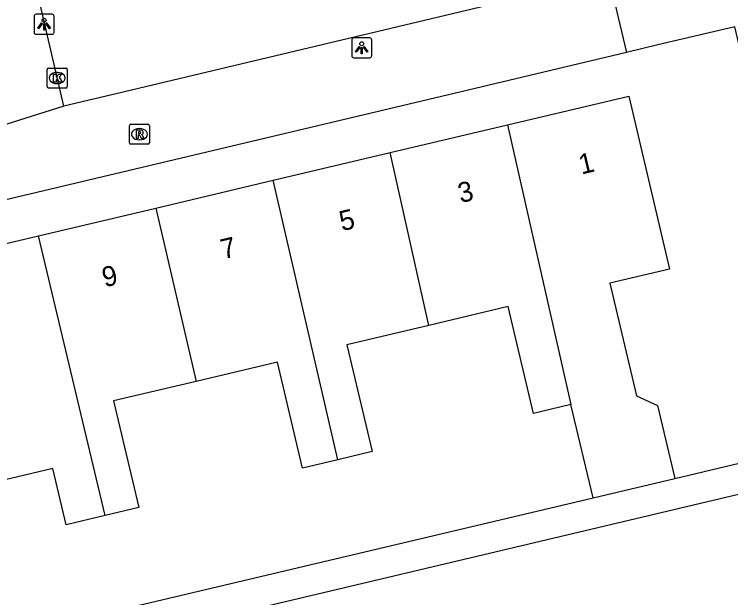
# Model space of a CAD drawing. Extents: x 158038 to 159242, y 380133 to 381214.
# Drawn here: x 158523.41 to 158559.26, y 380724.66 to 380753.87 of the extents above; entities that cross this region are included whole.
import ezdxf

# ---------------------------------------------------------------- set-up
doc = ezdxf.new("R2010")
doc.units = 0
for name, color, linetype in [('IMGEO_Kolk', 7, 'Continuous'), ('IMGEO_Lichtpunt', 7, 'Continuous'), ('IMGEO_Pand', 7, 'Continuous'), ('IMGEO_Pand_nummerreeks', 7, 'Continuous'), ('IMGEO_Rijbaan_lokaal_open', 7, 'Continuous'), ('IMGEO_Rioolput', 7, 'Continuous'), ('IMGEO_Voetpad_open', 7, 'Continuous')]:
    doc.layers.add(name, color=color, linetype=linetype)

msp = doc.modelspace()

# ---------------------------------------------------------------- linework, layer by layer
at = {"layer": 'IMGEO_Kolk'}
for p, q in [((158525.053, 380750.257), (158525.053, 380751.109)), ((158525.128, 380751.183), (158525.98, 380751.183)), ((158525.541, 380750.963), (158525.566, 380750.963)), ((158526.054, 380751.109), (158526.054, 380750.257)), ((158525.98, 380750.183), (158525.128, 380750.183)), ((158525.564, 380750.403), (158525.539, 380750.403))]:
    msp.add_line(p, q, dxfattribs=at)
for points in [[(158525.053, 380750.257), (158525.053, 380751.109)], [(158525.128, 380751.183), (158525.98, 380751.183)], [(158526.054, 380751.109), (158526.054, 380750.257)], [(158525.374, 380750.883), (158525.497, 380750.883), (158525.497, 380750.732), (158525.627, 380750.883), (158525.791, 380750.883), (158525.645, 380750.732), (158525.798, 380750.483), (158525.646, 380750.483), (158525.561, 380750.647), (158525.497, 380750.58), (158525.497, 380750.483), (158525.374, 380750.483), (158525.374, 380750.883)], [(158525.98, 380750.183), (158525.128, 380750.183)]]:
    msp.add_lwpolyline(points, dxfattribs=at)
for centre, start, end in [((158525.13, 380751.107), 91.552, 178.448), ((158525.13, 380751.107), 91.552, 178.448), ((158525.978, 380751.107), 1.552, 88.448), ((158525.978, 380751.107), 1.552, 88.448), ((158525.13, 380750.259), 181.552, 268.448), ((158525.13, 380750.259), 181.552, 268.448), ((158525.978, 380750.259), 271.552, 358.448), ((158525.978, 380750.259), 271.552, 358.448)]:
    msp.add_arc(centre, 0.0765, start, end, dxfattribs=at)
for centre, major_axis, ratio, start_param, end_param in [((158525.54, 380750.683), (-0.387, 0.002), 0.722429, 4.712389, 7.853982), ((158525.565, 380750.683), (-0.39, 0.002), 0.717154, 1.570796, 4.712389)]:
    msp.add_ellipse(centre, major_axis=major_axis, ratio=ratio, start_param=start_param, end_param=end_param, dxfattribs=at)
at = {"layer": 'IMGEO_Lichtpunt'}
for p, q in [((158524.4, 380753.779), (158524.4, 380752.972)), ((158524.4, 380753.779), (158524.4, 380752.972)), ((158525.302, 380753.874), (158524.494, 380753.874)), ((158525.302, 380753.874), (158524.494, 380753.874)), ((158525.396, 380752.972), (158525.396, 380753.779)), ((158525.396, 380752.972), (158525.396, 380753.779)), ((158524.494, 380752.878), (158525.302, 380752.878)), ((158524.494, 380752.878), (158525.302, 380752.878)), ((158541.199, 380752.696), (158540.391, 380752.696)), ((158541.199, 380752.696), (158540.391, 380752.696)), ((158540.297, 380752.601), (158540.297, 380751.794)), ((158540.297, 380752.601), (158540.297, 380751.794)), ((158541.293, 380751.794), (158541.293, 380752.601)), ((158541.293, 380751.794), (158541.293, 380752.601)), ((158540.391, 380751.7), (158541.199, 380751.7)), ((158540.391, 380751.7), (158541.199, 380751.7))]:
    msp.add_line(p, q, dxfattribs=at)
for points in [[(158524.774, 380753.443), (158524.813, 380753.415), (158524.625, 380753.153), (158524.587, 380753.18), (158524.774, 380753.443)], [(158524.986, 380753.415), (158525.024, 380753.442), (158525.211, 380753.18), (158525.172, 380753.152), (158524.986, 380753.415)], [(158524.876, 380753.395), (158524.923, 380753.395), (158524.923, 380753.073), (158524.876, 380753.073), (158524.876, 380753.395)], [(158540.671, 380752.265), (158540.71, 380752.237), (158540.522, 380751.975), (158540.484, 380752.002), (158540.671, 380752.265)], [(158540.773, 380752.217), (158540.82, 380752.217), (158540.82, 380751.895), (158540.773, 380751.895), (158540.773, 380752.217)], [(158540.883, 380752.237), (158540.921, 380752.264), (158541.108, 380752.002), (158541.069, 380751.974), (158540.883, 380752.237)]]:
    msp.add_lwpolyline(points, dxfattribs=at)
for centre in [(158524.899, 380753.577), (158540.796, 380752.399)]:
    msp.add_circle(centre, 0.0994, dxfattribs=at)
for centre, start, end in [((158524.494, 380753.779), 90, 180), ((158524.494, 380753.779), 90, 180), ((158525.302, 380753.779), 0, 90), ((158525.302, 380753.779), 0, 90), ((158524.494, 380752.972), 180, 270), ((158524.494, 380752.972), 180, 270), ((158525.302, 380752.972), 270, 0), ((158525.302, 380752.972), 270, 360), ((158540.391, 380752.601), 90, 180), ((158540.391, 380752.601), 90, 180), ((158541.199, 380752.601), 0, 90), ((158541.199, 380752.601), 0, 90), ((158540.391, 380751.794), 180, 270), ((158540.391, 380751.794), 180, 270), ((158541.199, 380751.794), 270, 0), ((158541.199, 380751.794), 270, 360)]:
    msp.add_arc(centre, 0.0946, start, end, dxfattribs=at)
at = {"layer": 'IMGEO_Pand'}
for points in [[(158548.086, 380748.344), (158554.154, 380749.781), (158556.205, 380741.118), (158553.218, 380740.411), (158554.554, 380734.767), (158555.592, 380734.295), (158556.459, 380730.636)], [(158542.212, 380746.953), (158548.086, 380748.344)], [(158548.086, 380748.344), (158551.265, 380734.335)], [(158536.368, 380745.569), (158542.212, 380746.953)], [(158544.152, 380738.299), (158542.212, 380746.953)], [(158530.486, 380744.176), (158536.368, 380745.569)], [(158539.599, 380731.57), (158536.368, 380745.569)], [(158524.623, 380742.787), (158530.486, 380744.176)], [(158530.486, 380744.176), (158532.5, 380735.491)], [(158518.537, 380741.346), (158524.623, 380742.787)], [(158527.954, 380728.778), (158524.623, 380742.787)], [(158527.954, 380728.778), (158525.999, 380728.315), (158525.332, 380731.135), (158521.188, 380730.153), (158520.589, 380732.683), (158519.689, 380736.481), (158519.042, 380739.212)], [(158551.265, 380734.335), (158549.395, 380733.892), (158548.128, 380739.241), (158544.152, 380738.299)], [(158544.152, 380738.299), (158540.055, 380737.329), (158541.322, 380731.978), (158539.599, 380731.57)], [(158539.599, 380731.57), (158537.828, 380731.151), (158536.571, 380736.455), (158532.5, 380735.491)], [(158532.5, 380735.491), (158528.377, 380734.514), (158529.641, 380729.177), (158527.954, 380728.778)], [(158552.37, 380729.668), (158551.265, 380734.335)], [(158552.37, 380729.668), (158556.459, 380730.636)]]:
    msp.add_lwpolyline(points, dxfattribs=at)
at = {"layer": 'IMGEO_Rijbaan_lokaal_open'}
for points in [[(158525.882, 380749.276), (158525.714, 380750), (158516.767, 380788.551)], [(158547.375, 380754.387), (158528.927, 380750), (158525.882, 380749.276)]]:
    msp.add_lwpolyline(points, dxfattribs=at)
at = {"layer": 'IMGEO_Rioolput'}
for p, q in [((158529.166, 380747.446), (158529.166, 380748.298)), ((158529.241, 380748.372), (158530.093, 380748.372)), ((158529.654, 380748.152), (158529.679, 380748.152)), ((158530.167, 380748.298), (158530.167, 380747.446)), ((158530.093, 380747.372), (158529.241, 380747.372)), ((158529.677, 380747.592), (158529.652, 380747.592))]:
    msp.add_line(p, q, dxfattribs=at)
for points in [[(158529.166, 380747.446), (158529.166, 380748.298)], [(158529.241, 380748.372), (158530.093, 380748.372)], [(158529.755, 380748.07), (158529.503, 380748.072), (158529.503, 380747.672)], [(158530.167, 380748.298), (158530.167, 380747.446)], [(158529.503, 380747.672), (158529.627, 380747.672), (158529.627, 380747.834), (158529.638, 380747.834)], [(158529.681, 380747.991), (158529.627, 380747.991), (158529.627, 380747.91)], [(158529.627, 380747.91), (158529.679, 380747.91)], [(158529.685, 380747.805), (158529.756, 380747.672), (158529.896, 380747.672), (158529.831, 380747.798)], [(158530.093, 380747.372), (158529.241, 380747.372)]]:
    msp.add_lwpolyline(points, dxfattribs=at)
for centre, radius, start, end in [((158529.243, 380748.296), 0.0765, 91.552, 178.448), ((158529.243, 380748.296), 0.0765, 91.552, 178.448), ((158529.754, 380747.96), 0.109, 350.3612, 89.416), ((158530.091, 380748.296), 0.0765, 1.552, 88.448), ((158530.091, 380748.296), 0.0765, 1.552, 88.448), ((158529.637, 380747.781), 0.0533, 26.0293, 88.6989), ((158529.663, 380748.099), 0.19, 274.7715, 282.9687), ((158529.687, 380747.895), 0.0964, 77.0061, 93.1865), ((158529.701, 380747.952), 0.0378, 276.6634, 79.6772), ((158529.752, 380747.96), 0.112, 277.5842, 350.9817), ((158529.736, 380747.745), 0.108, 29.5134, 73.7905), ((158529.243, 380747.448), 0.0765, 181.552, 268.448), ((158529.243, 380747.448), 0.0765, 181.552, 268.448), ((158530.091, 380747.448), 0.0765, 271.552, 358.448), ((158530.091, 380747.448), 0.0765, 271.552, 358.448)]:
    msp.add_arc(centre, radius, start, end, dxfattribs=at)
for centre, major_axis, ratio, start_param, end_param in [((158529.653, 380747.872), (-0.387, 0.002), 0.722429, 4.712389, 7.853982), ((158529.678, 380747.872), (-0.39, 0.002), 0.717154, 1.570796, 4.712389)]:
    msp.add_ellipse(centre, major_axis=major_axis, ratio=ratio, start_param=start_param, end_param=end_param, dxfattribs=at)
at = {"layer": 'IMGEO_Voetpad_open'}
for points in [[(158553.139, 380755.776), (158554.051, 380751.969)], [(158564.379, 380732.511), (158560.236, 380750), (158559.465, 380753.253), (158555.616, 380752.341), (158554.051, 380751.969)], [(158554.051, 380751.969), (158545.767, 380750), (158515.725, 380742.86)], [(158525.882, 380749.276), (158522.019, 380748.055)], [(158515.725, 380742.86), (158520.628, 380722.152), (158526.203, 380723.472), (158552.37, 380729.668)], [(158556.459, 380730.636), (158564.379, 380732.511)], [(158564.728, 380731.038), (158521.04, 380720.689), (158521.442, 380718.991), (158480.571, 380709.28)]]:
    msp.add_lwpolyline(points, dxfattribs=at)

# ---------------------------------------------------------------- texts
at = {"layer": 'IMGEO_Pand_nummerreeks'}
for s, p in [('1', (158551.785, 380745.849)), ('3', (158545.738, 380744.417)), ('5', (158539.802, 380743.011)), ('7', (158533.866, 380741.606)), ('9', (158527.93, 380740.2))]:
    msp.add_text(s, height=1, rotation=13.3236, dxfattribs=at).set_placement(p)

doc.saveas('drawing.dxf')
